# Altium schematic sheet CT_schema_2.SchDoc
size 238 x 312 mm
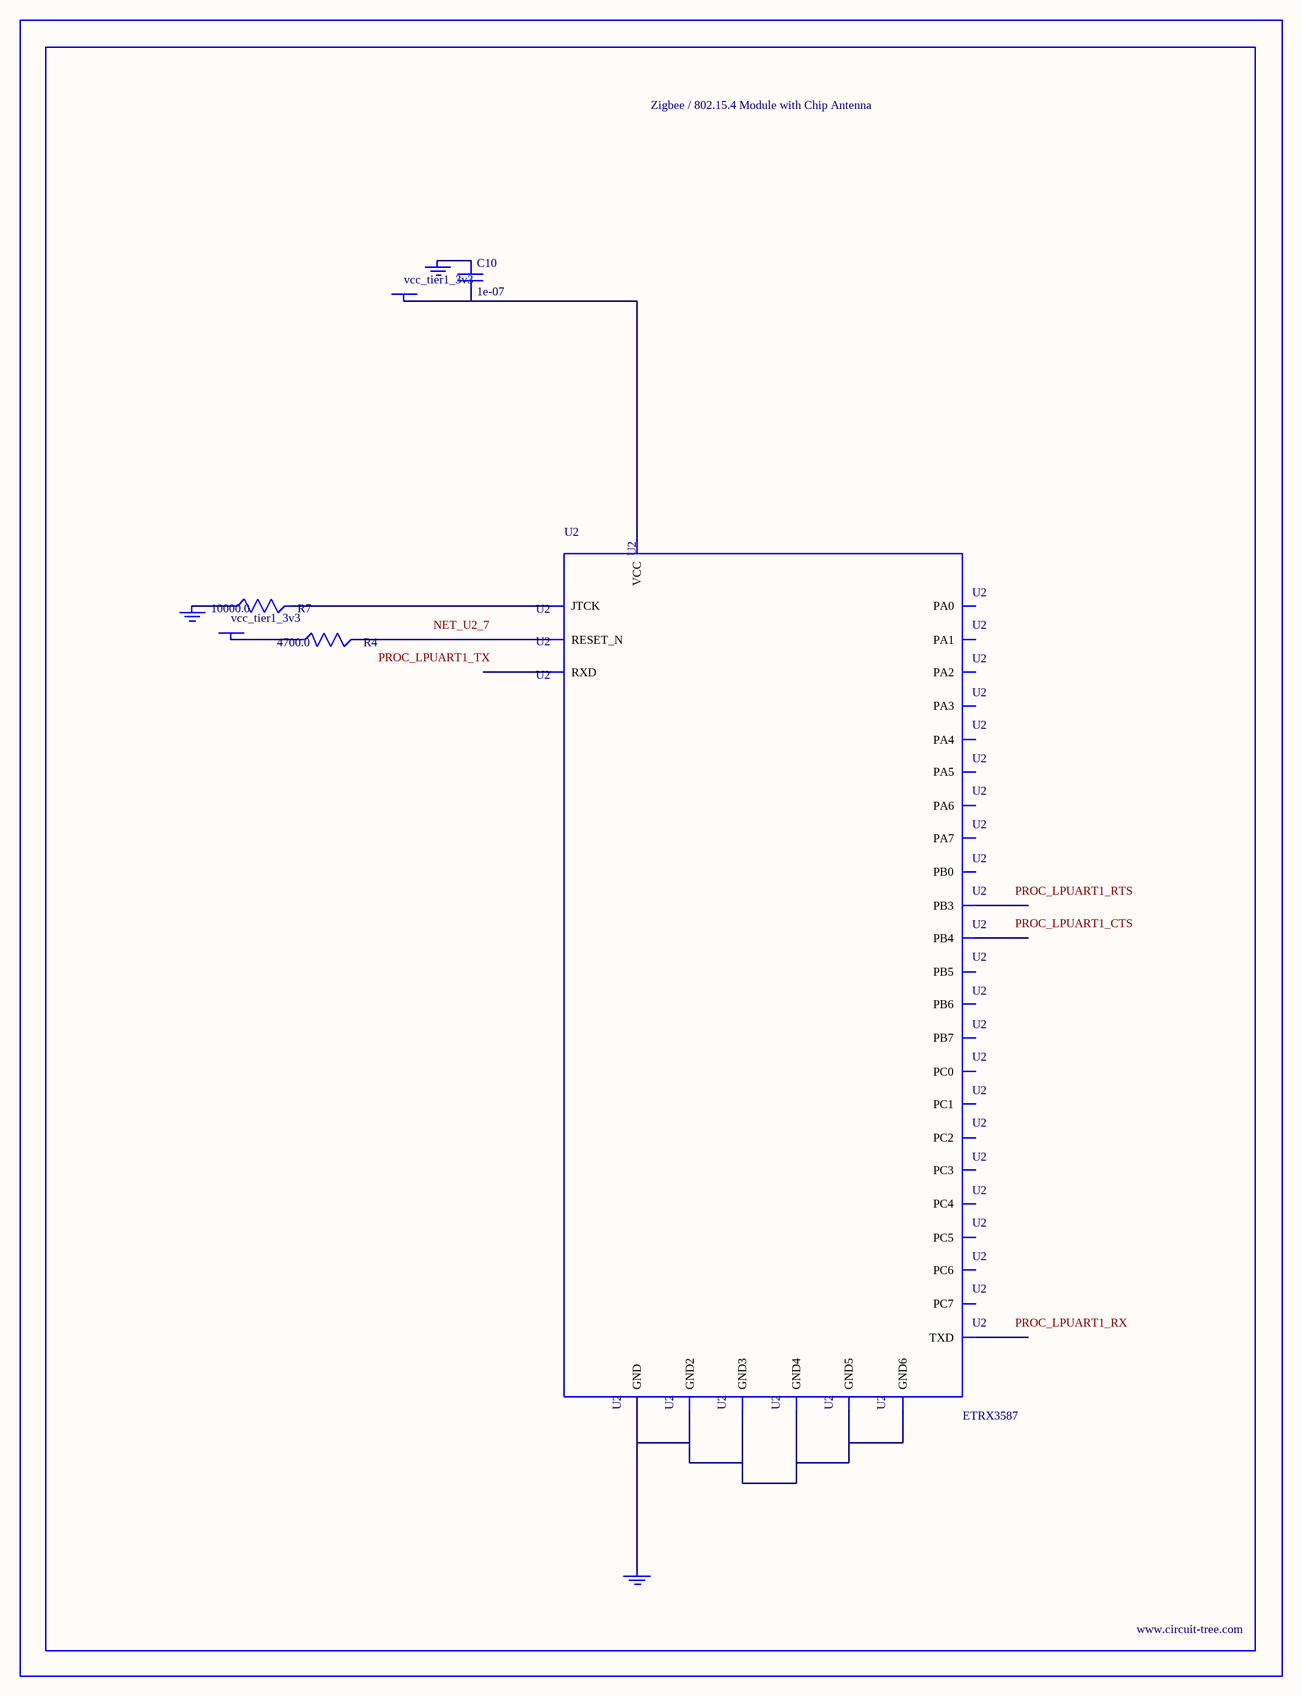
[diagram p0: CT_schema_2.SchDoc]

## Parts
BORDER1  (no value)
C10  1e-07  [C0402]
GND_INSTANCE_1_0  (no value)
GND_INSTANCE_1_1  (no value)
GND_INSTANCE_1_2  (no value)
POWER_INSTANCE_1_0  vcc_tier1_3v3
POWER_INSTANCE_1_1  vcc_tier1_3v3
R4  4700.0  [R0603]
R7  10000.0  [R0603]
U2  ETRX3587  [ETRX3587]

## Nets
NetC10_1: C10.1 GND_INSTANCE_1_1.0(GND)
NetC10_2: C10.2 POWER_INSTANCE_1_0.0(PWR) U2.32(VCC)
NetGND_INSTANCE_1_0_0: GND_INSTANCE_1_0.0(GND) R7.1
NetGND_INSTANCE_1_2_0: GND_INSTANCE_1_2.0(GND) U2.1(GND) U2.13(GND2) U2.19(GND3) U2.20(GND4) U2.31(GND5) U2.33(GND6)
NetPOWER_INSTANCE_1_1_0: POWER_INSTANCE_1_1.0(PWR) R4.1
NetR4_2: R4.2 U2.7(RESET_N)
NetR7_2: R7.2 U2.21(JTCK)

Not connected (* = marked no-connect by the designer): U2 2(PC5) 3(PC6) 4(PC7) 5(PA7) 6(PB3) 8(PB4) 9(PA0) 10(PA1) 11(PA2) 12(PA3) 14(PA4) 15(PA5) 16(PA6) 17(TXD) 18(RXD) 22(PC2) 23(PC3) 24(PC4) 25(PB0) 26(PC1) 27(PC0) 28(PB7) 29(PB6) 30(PB5)

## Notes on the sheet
- Labels drawn without touching a wire or pin: NET_U2_7, PROC_LPUART1_CTS, PROC_LPUART1_RTS, PROC_LPUART1_RX, PROC_LPUART1_TX

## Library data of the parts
BORDER1 = BORDER_PAGE1
C10 = C0402C104K3RACTU
GND_INSTANCE_1_0-GND_INSTANCE_1_2 = GND
POWER_INSTANCE_1_0 POWER_INSTANCE_1_1 = PWR
R4 = RC0603JR-074K7L
R7 = RC0603JR-0710KL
